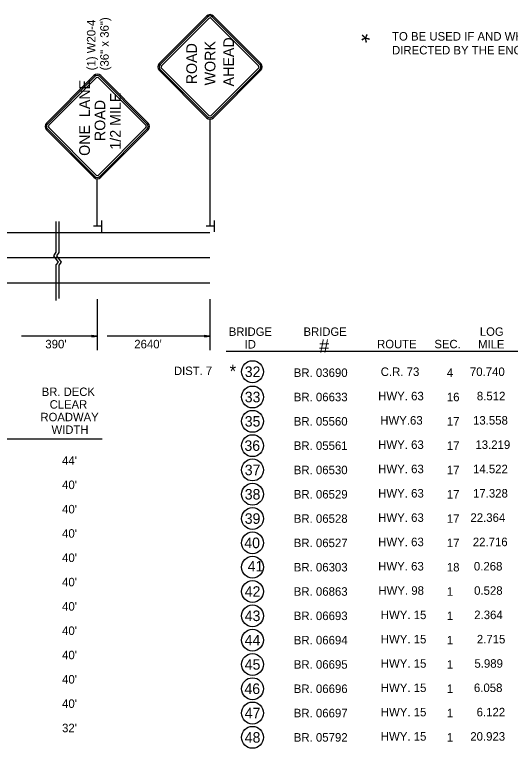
# Model space of a CAD drawing. Extents: x 1927831 to 1930787, y 596452 to 597699.
# Drawn here: x 1928485 to 1928834, y 596674 to 597191 of the extents above; entities that cross this region are included whole.
import ezdxf

# ---------------------------------------------------------------- set-up
doc = ezdxf.new("R2010")
doc.units = 0
for name, color, linetype in [('Default', 7, 'Continuous'), ('P_TC_Signs_Temporary', 7, 'Continuous'), ('R_Annotation', 7, 'Continuous')]:
    doc.layers.add(name, color=color, linetype=linetype)

msp = doc.modelspace()

# ---------------------------------------------------------------- linework, layer by layer
at = {"layer": 'Default'}
for p, q in [((1928546.3, 597045.75), (1928546.3, 597037.74)), ((1928625.68, 597045.75), (1928625.68, 597037.74)), ((1928546.18, 597041.76), (1928540.72, 597041.76)), ((1928625.56, 597041.76), (1928620.1, 597041.76)), ((1927841.07, 597037.34), (1928485.68, 597037.29)), ((1928485.68, 597037.29), (1928622.79, 597037.28)), ((1927840.35, 597019.55), (1928622.79, 597019.49)), ((1927840.85, 597001.76), (1928485.68, 597001.71)), ((1928485.68, 597001.71), (1928622.79, 597001.7)), ((1928543.49, 596954.25), (1928543.49, 596990.28)), ((1928622.83, 596954.25), (1928622.83, 596990.28)), ((1928543.49, 596964.29), (1928490.09, 596964.29)), ((1928539.65, 596964.87), (1928543.49, 596964.29)), ((1928539.65, 596964.87), (1928539.65, 596963.71)), ((1928539.65, 596964.77), (1928542.85, 596964.29)), ((1928539.65, 596964.67), (1928542.19, 596964.29)), ((1928539.65, 596964.58), (1928541.55, 596964.29)), ((1928539.65, 596964.48), (1928540.9, 596964.29)), ((1928539.65, 596964.38), (1928540.26, 596964.29)), ((1928539.65, 596963.71), (1928543.49, 596964.29)), ((1928539.65, 596964.1), (1928540.9, 596964.29)), ((1928539.65, 596963.91), (1928542.19, 596964.29)), ((1928539.65, 596963.81), (1928542.85, 596964.29)), ((1928539.65, 596964), (1928541.55, 596964.29)), ((1928539.65, 596964.2), (1928540.26, 596964.29)), ((1928622.83, 596964.29), (1928550.33, 596964.29)), ((1928618.99, 596964.87), (1928622.83, 596964.29)), ((1928618.99, 596964.87), (1928618.99, 596963.71)), ((1928618.99, 596964.77), (1928622.19, 596964.29)), ((1928618.99, 596964.67), (1928621.53, 596964.29)), ((1928618.99, 596964.58), (1928620.89, 596964.29)), ((1928618.99, 596964.48), (1928620.24, 596964.29)), ((1928618.99, 596964.38), (1928619.6, 596964.29)), ((1928618.99, 596963.71), (1928622.83, 596964.29)), ((1928618.99, 596964.1), (1928620.24, 596964.29)), ((1928618.99, 596963.91), (1928621.53, 596964.29)), ((1928618.99, 596963.81), (1928622.19, 596964.29)), ((1928618.99, 596964), (1928620.89, 596964.29)), ((1928618.99, 596964.2), (1928619.6, 596964.29))]:
    msp.add_line(p, q, dxfattribs=at)
for points in [[(1928514.36, 597044.83), (1928514.36, 597023.31), (1928512.7, 597020.84), (1928515.94, 597016.41), (1928514.23, 597014.36), (1928514.23, 596989.34)], [(1928516.4, 597045.03), (1928516.4, 597023.23), (1928514.74, 597020.75), (1928517.98, 597016.32), (1928516.28, 597014.28), (1928516.27, 596990.78)]]:
    msp.add_lwpolyline(points, dxfattribs=at)
for centre in [(1928652.72, 596939.17), (1928652.72, 596939.17), (1928652.72, 596921.37), (1928652.72, 596904.25), (1928652.72, 596887.14), (1928652.72, 596870.02), (1928652.72, 596852.9), (1928652.72, 596835.78), (1928652.72, 596818.66), (1928652.72, 596801.55), (1928652.72, 596784.43), (1928652.72, 596767.31), (1928652.72, 596750.19), (1928652.72, 596733.08), (1928652.72, 596715.96), (1928652.72, 596698.84), (1928652.72, 596681.72)]:
    msp.add_circle(centre, 7.71, dxfattribs=at)
at = {"layer": 'P_TC_Signs_Temporary'}
for p, q in [((1928587.03, 597156.16), (1928620.45, 597189.58)), ((1928587.7, 597155.5), (1928621.11, 597188.91)), ((1928624.56, 597188.91), (1928657.97, 597155.5)), ((1928625.22, 597189.58), (1928658.63, 597156.16)), ((1928588.63, 597154.57), (1928622.04, 597187.98)), ((1928623.63, 597187.98), (1928657.04, 597154.57)), ((1928621.11, 597118.64), (1928587.7, 597152.05)), ((1928622.04, 597119.57), (1928588.63, 597152.98)), ((1928657.04, 597152.98), (1928623.63, 597119.57)), ((1928657.97, 597152.05), (1928624.56, 597118.64)), ((1928507.65, 597114.24), (1928541.06, 597147.65)), ((1928508.32, 597113.58), (1928541.73, 597146.99)), ((1928545.17, 597146.99), (1928578.59, 597113.58)), ((1928545.84, 597147.65), (1928579.25, 597114.24)), ((1928620.45, 597117.98), (1928587.03, 597151.39)), ((1928658.63, 597151.39), (1928625.22, 597117.98)), ((1928509.24, 597112.65), (1928542.66, 597146.06)), ((1928544.25, 597146.06), (1928577.66, 597112.65)), ((1928542.66, 597077.65), (1928509.24, 597111.06)), ((1928577.66, 597111.06), (1928544.25, 597077.65)), ((1928541.06, 597076.06), (1928507.65, 597109.47)), ((1928541.73, 597076.72), (1928508.32, 597110.13)), ((1928578.59, 597110.13), (1928545.17, 597076.72)), ((1928579.25, 597109.47), (1928545.84, 597076.06))]:
    msp.add_line(p, q, dxfattribs=at)
for centre, radius, start, end in [((1928622.83, 597187.19), 3.38, 45, 135), ((1928622.83, 597187.19), 2.44, 45, 135), ((1928622.83, 597187.19), 1.12, 45, 135), ((1928589.42, 597153.78), 3.37, 135, 225), ((1928589.42, 597153.78), 2.44, 135, 225), ((1928589.42, 597153.78), 1.13, 135, 225), ((1928656.24, 597153.78), 1.13, 315, 45), ((1928656.24, 597153.78), 2.44, 315, 45), ((1928656.24, 597153.78), 3.37, 315, 45), ((1928543.45, 597145.27), 3.37, 45, 135), ((1928543.45, 597145.27), 2.44, 45, 135), ((1928543.45, 597145.27), 1.12, 45, 135), ((1928622.83, 597120.37), 3.37, 225, 315), ((1928622.83, 597120.37), 2.44, 225, 315), ((1928622.83, 597120.37), 1.12, 225, 315), ((1928510.04, 597111.86), 3.37, 135, 225), ((1928510.04, 597111.86), 2.44, 135, 225), ((1928510.04, 597111.86), 1.13, 135, 225), ((1928576.86, 597111.86), 1.13, 315, 45), ((1928576.86, 597111.86), 2.44, 315, 45), ((1928576.86, 597111.86), 3.37, 315, 45), ((1928543.45, 597078.44), 3.37, 225, 315), ((1928543.45, 597078.44), 2.44, 225, 315), ((1928543.45, 597078.44), 1.12, 225, 315)]:
    msp.add_arc(centre, radius, start, end, dxfattribs=at)
at = {"layer": 'R_Annotation'}
for p, q in [((1928622.83, 597041.76), (1928622.83, 597116.99)), ((1928543.45, 597041.76), (1928543.45, 597075.07)), ((1928634.16, 596953.74), (1928938.09, 596953.74)), ((1928242.96, 596891.91), (1928546.89, 596891.91))]:
    msp.add_line(p, q, dxfattribs=at)

# ---------------------------------------------------------------- texts
at = {"layer": 'Default'}
for s, p in [("390'", (1928506.85, 596955.63)), ("2640'", (1928569.46, 596955.63))]:
    msp.add_text(s, height=6, rotation=359.9922, dxfattribs=at).set_placement(p)
at = {"layer": 'P_TC_Signs_Temporary'}
for s, p in [(' AHEAD ', (1928639.67, 597137.24)), (' ROAD ', (1928613.62, 597138.76)), ('WORK', (1928626.64, 597140.79)), ('ONE  LANE', (1928538.2, 597091.16)), ('1/2 MILE', (1928559.95, 597095.54)), ('ROAD', (1928549.08, 597101.55))]:
    msp.add_text(s, height=7.5, rotation=90, dxfattribs=at).set_placement(p)
at = {"layer": 'R_Annotation'}
for s, height, rotation, p in [('(36" x 36")', 6, 90, (1928551.5, 597151.37)), ('(1) W20-4', 6, 90, (1928542.14, 597151.37)), ('TO BE USED IF AND WHERE', 6, 360, (1928750.97, 597172.32)), ('*', 12, 45, (1928736.26, 597165.59)), ('DIRECTED BY THE ENGINEER', 6, 360, (1928750.97, 597162.57)), ('BRIDGE ', 5.929, 360, (1928636.05, 596964.41)), ('BRIDGE ', 5.929, 360, (1928688.68, 596964.41)), ('LOG', 5.929, 360, (1928812.87, 596964.45)), ('ID', 5.929, 360, (1928647.23, 596955.52)), ('#', 9.5, 360, (1928699.67, 596952.55)), ('ROUTE', 5.929, 360, (1928740.53, 596955.68)), ('SEC.', 5.929, 360, (1928780.86, 596955.68)), ('MILE', 5.929, 360, (1928811.63, 596955.56)), ('DIST. 7', 5.929, 360, (1928597.45, 596936.86)), ('*', 9, 360, (1928636.59, 596935.08)), ('32', 7.412, 360, (1928647.29, 596935.46)), ('BR. 03690', 6, 360, (1928681.81, 596935.49)), ('C.R. 73', 6, 360, (1928743.04, 596936.17)), ('4', 6, 360, (1928789.59, 596935.49)), ('70.740', 6, 360, (1928805.84, 596936.17)), ('BR. DECK ', 5.929, 360, (1928504.32, 596922.09)), ('33', 7.412, 360, (1928647.29, 596917.66)), ('HWY. 63', 6, 360, (1928741.25, 596919.05)), ('8.512', 6, 360, (1928810.73, 596919.05)), ('BR. 06633', 6, 360, (1928681.81, 596918.37)), ('16', 6, 360, (1928789.59, 596918.37)), ('CLEAR', 5.929, 360, (1928509.9, 596913.19)), ('ROADWAY ', 5.929, 360, (1928503.43, 596904.3)), ('35', 7.412, 360, (1928647.29, 596900.55)), ('BR. 05560', 6, 360, (1928681.81, 596901.25)), ('HWY.63', 6, 360, (1928742.71, 596901.93)), ('17', 6, 360, (1928789.59, 596901.25)), ('13.558', 6, 360, (1928808.03, 596901.93)), ('WIDTH', 5.929, 360, (1928511.23, 596895.41)), ('36', 7.412, 360, (1928647.08, 596883.43)), ('BR. 05561', 6, 360, (1928681.81, 596884.14)), ('HWY. 63', 6, 360, (1928741.25, 596884.81)), ('17', 6, 360, (1928789.59, 596884.14)), ('13.219', 6, 360, (1928809.71, 596884.81)), ("44'", 6, 360, (1928518.63, 596873.66)), ('37', 7.412, 360, (1928647.29, 596866.31)), ('BR. 06530 ', 6, 360, (1928681.81, 596867.02)), ('HWY. 63', 6, 360, (1928741.25, 596867.7)), ('17', 6, 360, (1928789.59, 596867.02)), ('14.522', 6, 360, (1928808.03, 596867.7)), ("40'", 6, 360, (1928518.63, 596856.54)), ('38', 7.412, 360, (1928647.29, 596849.19)), ('BR. 06529', 6, 360, (1928681.81, 596849.9)), ('HWY. 63', 6, 360, (1928741.25, 596850.58)), ('17', 6, 360, (1928789.59, 596849.9)), ('17.328', 6, 360, (1928808.03, 596850.58)), ("40'", 6, 360, (1928518.63, 596839.42)), ('39', 7.412, 360, (1928647.26, 596832.08)), ('BR. 06528', 6, 360, (1928681.81, 596832.78)), ('HWY. 63', 6, 360, (1928741.25, 596833.46)), ('17', 6, 360, (1928789.59, 596832.78)), ('22.364', 6, 360, (1928806.19, 596833.46)), ("40'", 6, 360, (1928518.63, 596822.3)), ('40', 7.412, 360, (1928646.97, 596814.96)), ('BR. 06527', 6, 360, (1928681.81, 596815.66)), ('HWY. 63', 6, 360, (1928741.25, 596816.34)), ('17', 6, 360, (1928789.59, 596815.66)), ('22.716', 6, 360, (1928807.87, 596816.34)), ("40'", 6, 360, (1928518.63, 596805.19)), ('41', 7.412, 360, (1928649.39, 596798.58)), ('BR. 06303', 6, 360, (1928681.81, 596798.55)), ('HWY. 63', 6, 360, (1928741.25, 596799.22)), ('18', 6, 360, (1928789.59, 596798.55)), ('0.268', 6, 360, (1928808.65, 596799.22)), ("40'", 6, 360, (1928518.63, 596788.07)), ('42', 7.412, 360, (1928647.29, 596780.72)), ('BR. 06863', 6, 360, (1928681.81, 596781.43)), ('HWY. 98', 6, 360, (1928741.39, 596782.11)), ('1', 6, 360, (1928789.59, 596781.43)), ('0.528', 6, 360, (1928808.79, 596782.11)), ("40'", 6, 360, (1928518.63, 596770.95)), ('43', 7.412, 360, (1928647.29, 596763.61)), ('BR. 06693', 6, 360, (1928681.81, 596764.31)), ('HWY. 15', 6, 360, (1928743.09, 596764.99)), ('1', 6, 360, (1928789.59, 596764.31)), ('2.364', 6, 360, (1928808.88, 596764.99)), ("40'", 6, 360, (1928518.63, 596753.83)), ('44', 7.412, 360, (1928647.29, 596746.49)), ('BR. 06694', 6, 360, (1928681.81, 596747.19)), ('HWY. 15', 6, 360, (1928743.09, 596747.87)), ('1', 6, 360, (1928789.59, 596747.19)), ('2.715', 6, 360, (1928810.73, 596747.87)), ("40'", 6, 360, (1928518.63, 596736.72)), ('45', 7.412, 360, (1928647.29, 596729.37)), ('BR. 06695', 6, 360, (1928681.81, 596730.08)), ('HWY. 15', 6, 360, (1928743.09, 596730.75)), ('1', 6, 360, (1928789.59, 596730.08)), ('5.989', 6, 360, (1928809, 596730.75)), ("40'", 6, 360, (1928518.63, 596719.6)), ('46', 7.412, 360, (1928647.08, 596712.25)), ('BR. 06696', 6, 360, (1928681.81, 596712.96)), ('HWY. 15', 6, 360, (1928743.09, 596713.64)), ('1', 6, 360, (1928789.59, 596712.96)), ('6.058', 6, 360, (1928808.65, 596713.64)), ("40'", 6, 360, (1928518.63, 596702.48)), ('47', 7.412, 360, (1928647.29, 596695.14)), ('HWY. 15', 6, 360, (1928743.09, 596696.52)), ('6.122', 6, 360, (1928810.58, 596696.52)), ('BR. 06697', 6, 360, (1928681.81, 596695.84)), ('1', 6, 360, (1928789.59, 596695.84)), ("32'", 6, 360, (1928518.63, 596685.36)), ('48', 7.412, 360, (1928647.29, 596678.02)), ('BR. 05792', 6, 360, (1928681.81, 596678.72)), ('HWY. 15', 6, 360, (1928743.09, 596679.4)), ('1', 6, 360, (1928789.59, 596678.72)), ('20.923', 6, 360, (1928806.1, 596679.4))]:
    msp.add_text(s, height=height, rotation=rotation, dxfattribs=at).set_placement(p)

doc.saveas('drawing.dxf')
